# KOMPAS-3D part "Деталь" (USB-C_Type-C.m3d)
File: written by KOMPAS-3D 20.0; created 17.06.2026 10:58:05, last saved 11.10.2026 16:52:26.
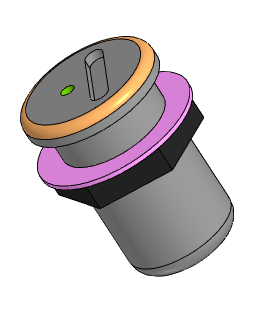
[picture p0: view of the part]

Document properties: Полное имя файла: D:\myProjects\Progect_esp32\box_compas\USB-C_Type-C.m3d

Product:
- Part/product: Деталь
    Масса: 0.0197779
  - Body: Тело 1
      Масса: 0.0200027

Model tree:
1. Эскиз:1
2. Элемент выдавливания:1
     Расстояние 1 = 2
3. Эскиз:2  (with: Элемент выдавливания:1)
4. Элемент выдавливания:2
     Расстояние 1 = 19
5. Скругление:1  (with: Элемент выдавливания:1)
     Радиус = 1
6. Эскиз:4  (with: Элемент выдавливания:1, Скругление:1)
7. Элемент выдавливания:4
     Расстояние 2 = 1
8. Скругление:3  (with: Элемент выдавливания:4)
     Радиус = 1
9. Смещенная плоскость:1  (with: Элемент выдавливания:1)
     Расстояние = 4.5
10. Эскиз:5
11. Элемент выдавливания:5
     Расстояние 1 = 3
12. Эскиз:6  (with: Элемент выдавливания:2)
13. Элемент выдавливания:6
     Расстояние 1 = 0.5
14. Скругление:4  (with: Элемент выдавливания:2)
     Радиус = 2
